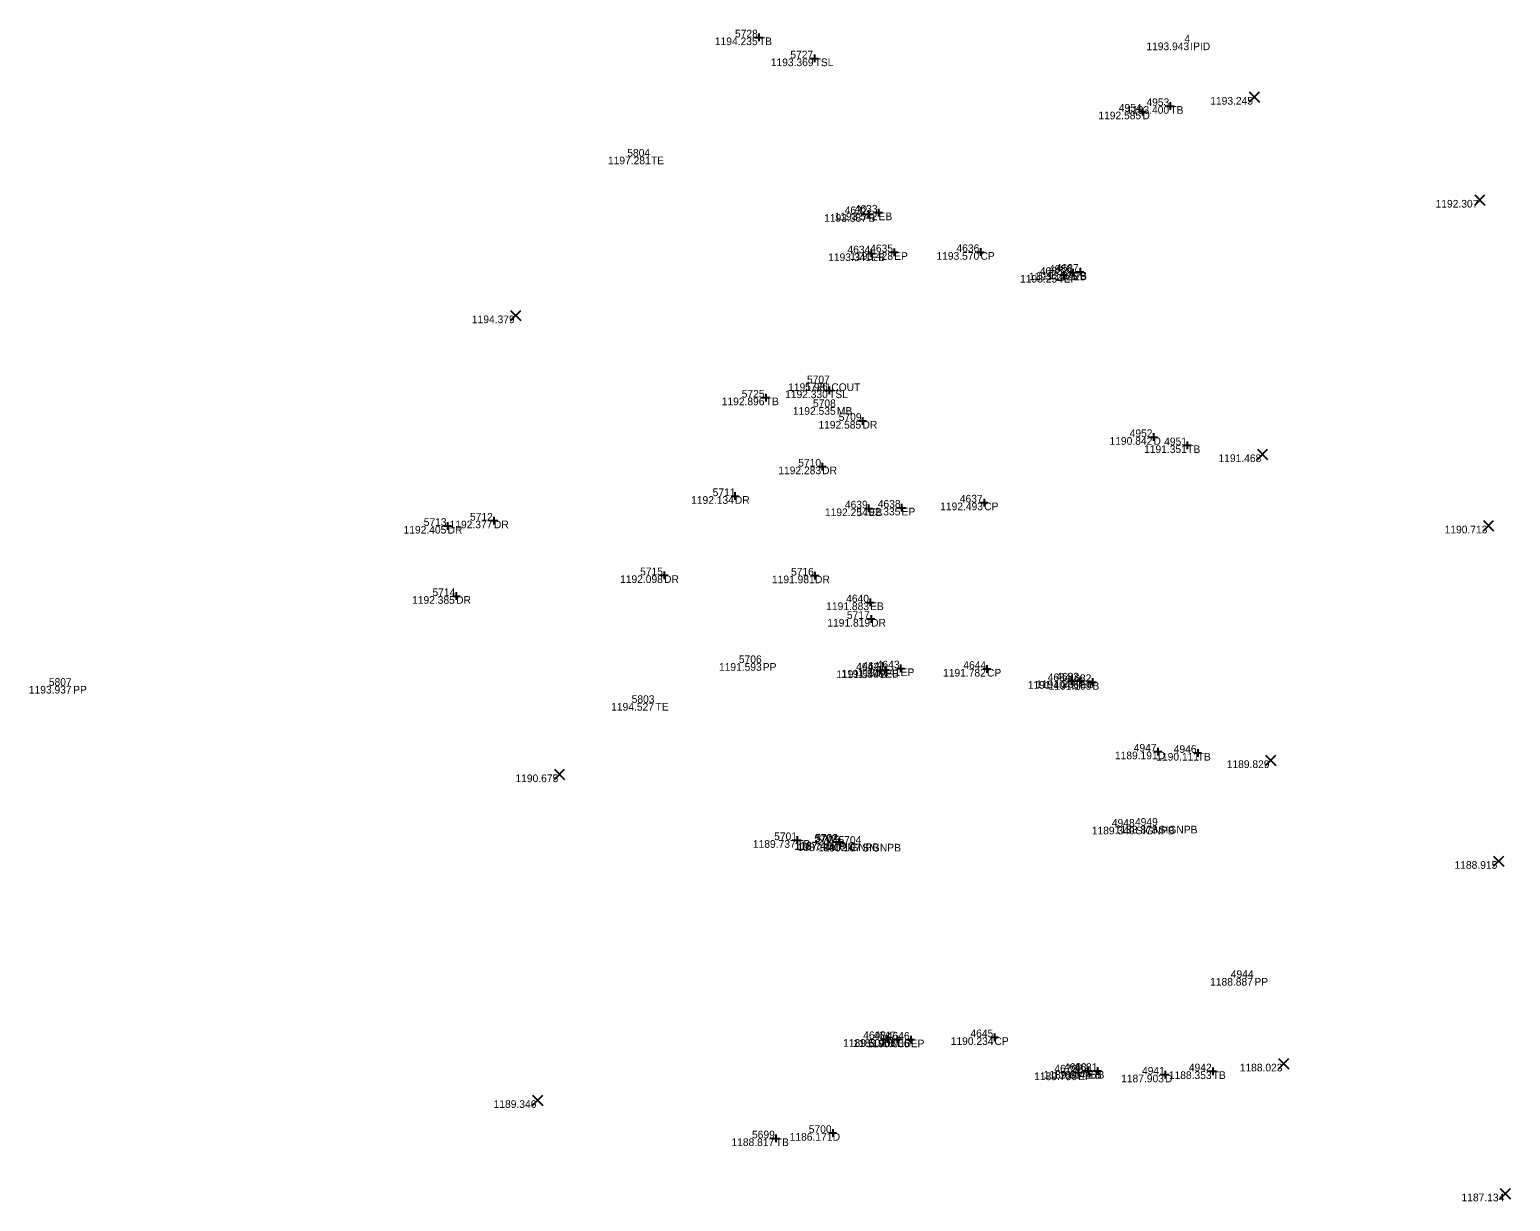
# Model space of a CAD drawing. Extents: x 2044997 to 2050342, y 455233 to 458054.
# Drawn here: x 2047524.4 to 2047717.5, y 456155.7 to 456308.4 of the extents above; entities that cross this region are included whole.
import ezdxf

# ---------------------------------------------------------------- set-up
doc = ezdxf.new("R2010")
doc.units = 0
for name, color, linetype in [('SV_X_Random_Point', 7, 'Continuous'), ('SV_X_Shot_Marker', 7, 'Continuous'), ('SV_X_Text_Comment', 7, 'Continuous'), ('SV_X_Text_Elevation', 7, 'Continuous'), ('SV_X_Text_Name', 7, 'Continuous')]:
    doc.layers.add(name, color=color, linetype=linetype)

msp = doc.modelspace()

# ---------------------------------------------------------------- linework, layer by layer
at = {"layer": 'SV_X_Random_Point'}
for p, q in [((2047683.45, 456298.97), (2047684.78, 456300.31)), ((2047683.45, 456300.31), (2047684.78, 456298.97)), ((2047712.86, 456285.55), (2047714.19, 456286.89)), ((2047712.86, 456286.89), (2047714.19, 456285.55)), ((2047587.15, 456270.48), (2047588.49, 456271.81)), ((2047587.15, 456271.81), (2047588.49, 456270.48)), ((2047684.52, 456252.38), (2047685.85, 456253.72)), ((2047684.52, 456253.72), (2047685.85, 456252.38)), ((2047713.99, 456243.08), (2047715.32, 456244.41)), ((2047713.99, 456244.41), (2047715.32, 456243.08)), ((2047685.57, 456212.49), (2047686.91, 456213.82)), ((2047685.57, 456213.82), (2047686.91, 456212.49)), ((2047592.86, 456210.65), (2047594.19, 456211.99)), ((2047592.86, 456211.99), (2047594.19, 456210.65)), ((2047715.3, 456199.35), (2047716.63, 456200.69)), ((2047715.3, 456200.69), (2047716.63, 456199.35)), ((2047687.26, 456172.94), (2047688.6, 456174.28)), ((2047687.26, 456174.28), (2047688.6, 456172.94)), ((2047590.01, 456168.18), (2047591.34, 456169.52)), ((2047590.01, 456169.52), (2047591.34, 456168.18)), ((2047716.17, 456156.01), (2047717.5, 456157.35)), ((2047716.17, 456157.35), (2047717.5, 456156.01))]:
    msp.add_line(p, q, dxfattribs=at)
at = {"layer": 'SV_X_Shot_Marker'}
for p, q in [((2047619.02, 456307.4), (2047620.02, 456307.4)), ((2047619.52, 456307.9), (2047619.52, 456306.9)), ((2047619.52, 456307.4), (2047619.52, 456307.4)), ((2047626.28, 456304.66), (2047627.28, 456304.66)), ((2047626.78, 456305.16), (2047626.78, 456304.16)), ((2047626.78, 456304.66), (2047626.78, 456304.66)), ((2047672.66, 456298.45), (2047673.66, 456298.45)), ((2047673.16, 456298.95), (2047673.16, 456297.95)), ((2047673.16, 456298.45), (2047673.16, 456298.45)), ((2047669.03, 456297.73), (2047670.03, 456297.73)), ((2047669.53, 456298.23), (2047669.53, 456297.23)), ((2047669.53, 456297.73), (2047669.53, 456297.73)), ((2047633.81, 456284.87), (2047633.81, 456283.87)), ((2047635.12, 456285.07), (2047635.12, 456284.07)), ((2047633.31, 456284.37), (2047634.31, 456284.37)), ((2047633.81, 456284.37), (2047633.81, 456284.37)), ((2047634.62, 456284.57), (2047635.62, 456284.57)), ((2047635.12, 456284.57), (2047635.12, 456284.57)), ((2047633.66, 456279.25), (2047634.66, 456279.25)), ((2047634.16, 456279.75), (2047634.16, 456278.75)), ((2047634.16, 456279.25), (2047634.16, 456279.25)), ((2047636.66, 456279.4), (2047637.66, 456279.4)), ((2047637.16, 456279.9), (2047637.16, 456278.9)), ((2047637.16, 456279.4), (2047637.16, 456279.4)), ((2047647.91, 456279.42), (2047648.91, 456279.42)), ((2047648.41, 456279.92), (2047648.41, 456278.92)), ((2047648.41, 456279.42), (2047648.41, 456279.42)), ((2047660.46, 456277.24), (2047660.46, 456276.24)), ((2047661.4, 456277.35), (2047661.4, 456276.35)), ((2047658.77, 456276.44), (2047659.77, 456276.44)), ((2047659.27, 456276.94), (2047659.27, 456275.94)), ((2047659.27, 456276.44), (2047659.27, 456276.44)), ((2047659.96, 456276.74), (2047660.96, 456276.74)), ((2047660.46, 456276.74), (2047660.46, 456276.74)), ((2047660.9, 456276.85), (2047661.9, 456276.85)), ((2047661.4, 456276.85), (2047661.4, 456276.85)), ((2047628.67, 456261.88), (2047628.67, 456260.88)), ((2047619.91, 456260.45), (2047620.91, 456260.45)), ((2047620.41, 456260.95), (2047620.41, 456259.95)), ((2047620.41, 456260.45), (2047620.41, 456260.45)), ((2047628.17, 456261.38), (2047629.17, 456261.38)), ((2047628.67, 456261.38), (2047628.67, 456261.38)), ((2047633.03, 456257.91), (2047633.03, 456256.91)), ((2047632.53, 456257.41), (2047633.53, 456257.41)), ((2047633.03, 456257.41), (2047633.03, 456257.41)), ((2047670.47, 456255.3), (2047671.47, 456255.3)), ((2047670.97, 456255.8), (2047670.97, 456254.8)), ((2047670.97, 456255.3), (2047670.97, 456255.3)), ((2047674.86, 456254.23), (2047675.86, 456254.23)), ((2047675.36, 456254.73), (2047675.36, 456253.73)), ((2047675.36, 456254.23), (2047675.36, 456254.23)), ((2047627.27, 456251.46), (2047628.27, 456251.46)), ((2047627.77, 456251.96), (2047627.77, 456250.96)), ((2047627.77, 456251.46), (2047627.77, 456251.46)), ((2047615.89, 456247.6), (2047616.89, 456247.6)), ((2047616.39, 456248.1), (2047616.39, 456247.1)), ((2047616.39, 456247.6), (2047616.39, 456247.6)), ((2047633.83, 456246.5), (2047633.83, 456245.5)), ((2047638.13, 456246.59), (2047638.13, 456245.59)), ((2047648.39, 456246.77), (2047649.39, 456246.77)), ((2047648.89, 456247.27), (2047648.89, 456246.27)), ((2047648.89, 456246.77), (2047648.89, 456246.77)), ((2047584.47, 456244.41), (2047585.47, 456244.41)), ((2047584.97, 456244.91), (2047584.97, 456243.91)), ((2047584.97, 456244.41), (2047584.97, 456244.41)), ((2047633.33, 456246), (2047634.33, 456246)), ((2047633.83, 456246), (2047633.83, 456246)), ((2047637.63, 456246.09), (2047638.63, 456246.09)), ((2047638.13, 456246.09), (2047638.13, 456246.09)), ((2047578.43, 456243.72), (2047579.43, 456243.72)), ((2047578.93, 456244.22), (2047578.93, 456243.22)), ((2047578.93, 456243.72), (2047578.93, 456243.72)), ((2047606.66, 456237.28), (2047607.66, 456237.28)), ((2047607.16, 456237.78), (2047607.16, 456236.78)), ((2047607.16, 456237.28), (2047607.16, 456237.28)), ((2047626.33, 456237.25), (2047627.33, 456237.25)), ((2047626.83, 456237.75), (2047626.83, 456236.75)), ((2047626.83, 456237.25), (2047626.83, 456237.25)), ((2047580.05, 456235.07), (2047580.05, 456234.07)), ((2047579.55, 456234.57), (2047580.55, 456234.57)), ((2047580.05, 456234.57), (2047580.05, 456234.57)), ((2047633.52, 456233.75), (2047634.52, 456233.75)), ((2047634.02, 456234.25), (2047634.02, 456233.25)), ((2047634.02, 456233.75), (2047634.02, 456233.75)), ((2047633.65, 456231.6), (2047634.65, 456231.6)), ((2047634.15, 456232.1), (2047634.15, 456231.1)), ((2047634.15, 456231.6), (2047634.15, 456231.6)), ((2047635.31, 456225.38), (2047635.31, 456224.38)), ((2047636, 456225.46), (2047636, 456224.46)), ((2047637.5, 456225.15), (2047638.5, 456225.15)), ((2047638, 456225.65), (2047638, 456224.65)), ((2047638, 456225.15), (2047638, 456225.15)), ((2047648.76, 456225.08), (2047649.76, 456225.08)), ((2047649.26, 456225.58), (2047649.26, 456224.58)), ((2047649.26, 456225.08), (2047649.26, 456225.08)), ((2047634.81, 456224.88), (2047635.81, 456224.88)), ((2047635.31, 456224.88), (2047635.31, 456224.88)), ((2047635.5, 456224.96), (2047636.5, 456224.96)), ((2047636, 456224.96), (2047636, 456224.96)), ((2047659.77, 456223.49), (2047660.77, 456223.49)), ((2047660.27, 456223.99), (2047660.27, 456222.99)), ((2047660.27, 456223.49), (2047660.27, 456223.49)), ((2047660.9, 456223.57), (2047661.9, 456223.57)), ((2047661.4, 456224.07), (2047661.4, 456223.07)), ((2047661.4, 456223.57), (2047661.4, 456223.57)), ((2047662.51, 456223.37), (2047663.51, 456223.37)), ((2047663.01, 456223.87), (2047663.01, 456222.87)), ((2047663.01, 456223.37), (2047663.01, 456223.37)), ((2047671.05, 456214.3), (2047672.05, 456214.3)), ((2047671.55, 456214.8), (2047671.55, 456213.8)), ((2047671.55, 456214.3), (2047671.55, 456214.3)), ((2047676.23, 456214.13), (2047677.23, 456214.13)), ((2047676.73, 456214.63), (2047676.73, 456213.63)), ((2047676.73, 456214.13), (2047676.73, 456214.13)), ((2047624.01, 456202.76), (2047625.01, 456202.76)), ((2047624.51, 456203.26), (2047624.51, 456202.26)), ((2047624.51, 456202.76), (2047624.51, 456202.76)), ((2047629.47, 456202.55), (2047630.47, 456202.55)), ((2047629.97, 456203.05), (2047629.97, 456202.05)), ((2047629.97, 456202.55), (2047629.97, 456202.55)), ((2047635.73, 456176.82), (2047636.73, 456176.82)), ((2047636.23, 456177.32), (2047636.23, 456176.32)), ((2047636.23, 456176.82), (2047636.23, 456176.82)), ((2047637.06, 456176.8), (2047638.06, 456176.8)), ((2047637.56, 456177.3), (2047637.56, 456176.3)), ((2047637.56, 456176.8), (2047637.56, 456176.8)), ((2047638.82, 456176.75), (2047639.82, 456176.75)), ((2047639.32, 456177.25), (2047639.32, 456176.25)), ((2047639.32, 456176.75), (2047639.32, 456176.75)), ((2047649.73, 456177.06), (2047650.73, 456177.06)), ((2047650.23, 456177.56), (2047650.23, 456176.56)), ((2047650.23, 456177.06), (2047650.23, 456177.06)), ((2047661.14, 456172.97), (2047661.14, 456171.97)), ((2047662.43, 456173.18), (2047662.43, 456172.18)), ((2047663.68, 456173.17), (2047663.68, 456172.17)), ((2047678.69, 456173.12), (2047678.69, 456172.12)), ((2047660.64, 456172.47), (2047661.64, 456172.47)), ((2047661.14, 456172.47), (2047661.14, 456172.47)), ((2047661.93, 456172.68), (2047662.93, 456172.68)), ((2047662.43, 456172.68), (2047662.43, 456172.68)), ((2047663.18, 456172.67), (2047664.18, 456172.67)), ((2047663.68, 456172.67), (2047663.68, 456172.67)), ((2047671.97, 456172.19), (2047672.97, 456172.19)), ((2047672.47, 456172.69), (2047672.47, 456171.69)), ((2047672.47, 456172.19), (2047672.47, 456172.19)), ((2047678.19, 456172.62), (2047679.19, 456172.62)), ((2047678.69, 456172.62), (2047678.69, 456172.62)), ((2047621.22, 456163.88), (2047622.22, 456163.88)), ((2047621.72, 456164.38), (2047621.72, 456163.38)), ((2047621.72, 456163.88), (2047621.72, 456163.88)), ((2047628.64, 456164.58), (2047629.64, 456164.58)), ((2047629.14, 456165.08), (2047629.14, 456164.08)), ((2047629.14, 456164.58), (2047629.14, 456164.58))]:
    msp.add_line(p, q, dxfattribs=at)

# ---------------------------------------------------------------- texts
at = {"layer": 'SV_X_Text_Comment'}
for s, p in [('TB', (2047619.52, 456306.4)), ('IPID', (2047675.76, 456305.74)), ('TSL', (2047626.78, 456303.66)), ('TB', (2047673.16, 456297.45)), ('D', (2047669.53, 456296.73)), ('TE', (2047605.45, 456290.86)), ('B', (2047633.81, 456283.37)), ('EB', (2047635.12, 456283.57)), ('EB', (2047634.16, 456278.25)), ('EP', (2047637.16, 456278.4)), ('CP', (2047648.41, 456278.42)), ('EP', (2047659.27, 456275.44)), ('EB', (2047660.46, 456275.74)), ('B', (2047661.4, 456275.85)), ('COUT', (2047628.96, 456261.31)), ('TB', (2047620.41, 456259.45)), ('TSL', (2047628.67, 456260.38)), ('MB', (2047629.69, 456258.21)), ('DR', (2047633.03, 456256.41)), ('D', (2047670.97, 456254.3)), ('TB', (2047675.36, 456253.23)), ('DR', (2047627.77, 456250.46)), ('DR', (2047616.39, 456246.6)), ('CP', (2047648.89, 456245.77)), ('DR', (2047584.97, 456243.41)), ('EB', (2047633.83, 456245)), ('EP', (2047638.13, 456245.09)), ('DR', (2047578.93, 456242.72)), ('DR', (2047607.16, 456236.28)), ('DR', (2047626.83, 456236.25)), ('DR', (2047580.05, 456233.57)), ('EB', (2047634.02, 456232.75)), ('DR', (2047634.15, 456230.6)), ('PP', (2047620.03, 456224.84)), ('EP', (2047638, 456224.15)), ('CP', (2047649.26, 456224.08)), ('B', (2047635.31, 456223.88)), ('EB', (2047636, 456223.96)), ('EP', (2047660.27, 456222.49)), ('EB', (2047661.4, 456222.57)), ('B', (2047663.01, 456222.37)), ('PP', (2047530.11, 456221.87)), ('TE', (2047606.04, 456219.64)), ('D', (2047671.55, 456213.3)), ('TB', (2047676.73, 456213.13)), ('SIGNPB', (2047668.66, 456203.51)), ('SIGNPB', (2047671.65, 456203.63)), ('TB', (2047624.51, 456201.76)), ('PIO', (2047629.87, 456201.49)), ('D', (2047629.97, 456201.55)), ('SIGNPB', (2047630.17, 456201.33)), ('SIGNPB', (2047632.99, 456201.28)), ('PP', (2047684.13, 456183.79)), ('B', (2047636.23, 456175.82)), ('EB', (2047637.56, 456175.8)), ('EP', (2047639.32, 456175.75)), ('CP', (2047650.23, 456176.06)), ('EP', (2047661.14, 456171.47)), ('EB', (2047662.43, 456171.68)), ('B', (2047663.68, 456171.67)), ('D', (2047672.47, 456171.19)), ('TB', (2047678.69, 456171.62)), ('TB', (2047621.72, 456162.88)), ('D', (2047629.14, 456163.58))]:
    msp.add_text(s, height=1, dxfattribs=at).set_placement(p)
at = {"layer": 'SV_X_Text_Elevation'}
for s, p in [('1194.235', (2047613.78, 456306.4)), ('1193.943', (2047670.04, 456305.74)), ('1193.369', (2047621.07, 456303.66)), ('1193.400', (2047667.43, 456297.45)), ('1193.245', (2047678.37, 456298.64)), ('1192.585', (2047663.78, 456296.73)), ('1197.281', (2047599.84, 456290.86)), ('1192.307', (2047707.75, 456285.22)), ('1193.387', (2047628.03, 456283.37)), ('1193.542', (2047629.39, 456283.57)), ('1193.341', (2047628.55, 456278.25)), ('1193.428', (2047631.43, 456278.4)), ('1193.570', (2047642.67, 456278.42)), ('1193.254', (2047653.57, 456275.44)), ('1193.122', (2047654.73, 456275.74)), ('1192.849', (2047655.69, 456275.85)), ('1194.379', (2047582.1, 456270.15)), ('1191.981', (2047623.34, 456261.31)), ('1192.896', (2047614.67, 456259.45)), ('1192.330', (2047622.93, 456260.38)), ('1192.535', (2047623.95, 456258.21)), ('1192.585', (2047627.28, 456256.41)), ('1190.842', (2047665.24, 456254.3)), ('1191.351', (2047669.74, 456253.23)), ('1191.468', (2047679.45, 456252.05)), ('1192.283', (2047622.05, 456250.46)), ('1192.134', (2047610.68, 456246.6)), ('1192.493', (2047643.16, 456245.77)), ('1192.377', (2047579.19, 456243.41)), ('1192.254', (2047628.13, 456245)), ('1192.335', (2047632.39, 456245.09)), ('1192.405', (2047573.19, 456242.72)), ('1190.713', (2047708.93, 456242.75)), ('1192.098', (2047601.42, 456236.28)), ('1191.981', (2047621.22, 456236.25)), ('1192.385', (2047574.3, 456233.57)), ('1191.883', (2047628.3, 456232.75)), ('1191.819', (2047628.44, 456230.6)), ('1191.593', (2047614.31, 456224.84)), ('1191.641', (2047632.39, 456224.15)), ('1191.782', (2047643.53, 456224.08)), ('1191.544', (2047629.61, 456223.88)), ('1191.596', (2047630.26, 456223.96)), ('1191.404', (2047654.57, 456222.49)), ('1191.286', (2047655.66, 456222.57)), ('1191.109', (2047657.3, 456222.37)), ('1193.937', (2047524.33, 456221.87)), ('1194.527', (2047600.26, 456219.64)), ('1189.191', (2047665.94, 456213.3)), ('1190.111', (2047671.33, 456213.13)), ('1189.829', (2047680.52, 456212.16)), ('1190.675', (2047587.78, 456210.32)), ('1189.340', (2047662.92, 456203.51)), ('1188.878', (2047665.92, 456203.63)), ('1189.737', (2047618.74, 456201.76)), ('1187.410', (2047624.14, 456201.49)), ('1187.407', (2047624.2, 456201.55)), ('1187.241', (2047624.56, 456201.33)), ('1190.167', (2047627.22, 456201.28)), ('1188.915', (2047710.22, 456199.02)), ('1188.887', (2047678.35, 456183.79)), ('1189.502', (2047630.5, 456175.82)), ('1189.908', (2047631.83, 456175.8)), ('1190.006', (2047633.58, 456175.75)), ('1190.234', (2047644.53, 456176.06)), ('1188.023', (2047682.21, 456172.61)), ('1189.730', (2047655.41, 456171.47)), ('1189.617', (2047656.65, 456171.68)), ('1189.496', (2047657.95, 456171.67)), ('1187.903', (2047666.75, 456171.19)), ('1188.353', (2047672.97, 456171.62)), ('1189.346', (2047584.93, 456167.85)), ('1188.817', (2047615.94, 456162.88)), ('1186.171', (2047623.53, 456163.58)), ('1187.134', (2047711.13, 456155.68))]:
    msp.add_text(s, height=1, dxfattribs=at).set_placement(p)
at = {"layer": 'SV_X_Text_Name'}
for s, p in [('5728', (2047616.4, 456307.4)), ('4', (2047675, 456306.74)), ('5727', (2047623.62, 456304.66)), ('4954', (2047666.44, 456297.73)), ('4953', (2047670.05, 456298.45)), ('5804', (2047602.36, 456291.86)), ('4632', (2047630.7, 456284.37)), ('4633', (2047632.02, 456284.57)), ('4634', (2047631.07, 456279.25)), ('4635', (2047634.03, 456279.4)), ('4636', (2047645.28, 456279.42)), ('4685', (2047656.14, 456276.44)), ('4686', (2047657.34, 456276.74)), ('4687', (2047658.24, 456276.85)), ('5726', (2047625.54, 456261.38)), ('5707', (2047625.79, 456262.31)), ('5725', (2047617.28, 456260.45)), ('5708', (2047626.57, 456259.21)), ('5709', (2047629.93, 456257.41)), ('4952', (2047667.86, 456255.3)), ('4951', (2047672.36, 456254.23)), ('5710', (2047624.65, 456251.46)), ('5711', (2047613.49, 456247.6)), ('4639', (2047630.73, 456246)), ('4638', (2047635.02, 456246.09)), ('4637', (2047645.72, 456246.77)), ('5713', (2047575.82, 456243.72)), ('5712', (2047581.85, 456244.41)), ('5715', (2047604.03, 456237.28)), ('5716', (2047623.71, 456237.25)), ('5714', (2047576.96, 456234.57)), ('4640', (2047630.9, 456233.75)), ('5717', (2047630.99, 456231.6)), ('5706', (2047616.91, 456225.84)), ('4642', (2047632.2, 456224.88)), ('4641', (2047633, 456224.96)), ('4643', (2047634.89, 456225.15)), ('4644', (2047646.17, 456225.08)), ('5807', (2047526.94, 456222.87)), ('4684', (2047657.18, 456223.49)), ('4683', (2047658.29, 456223.57)), ('4682', (2047659.89, 456223.37)), ('5803', (2047602.93, 456220.64)), ('4947', (2047668.39, 456214.3)), ('4946', (2047673.61, 456214.13)), ('5701', (2047621.51, 456202.76)), ('4948', (2047665.54, 456204.51)), ('4949', (2047668.55, 456204.63)), ('5703', (2047626.76, 456202.49)), ('5702', (2047626.86, 456202.55)), ('5705', (2047627.04, 456202.33)), ('5704', (2047629.9, 456202.28)), ('4944', (2047681.04, 456184.79)), ('4648', (2047633.12, 456176.82)), ('4647', (2047634.4, 456176.8)), ('4646', (2047636.2, 456176.75)), ('4645', (2047647.1, 456177.06)), ('4679', (2047658.04, 456172.47)), ('4680', (2047659.31, 456172.68)), ('4681', (2047660.68, 456172.67)), ('4941', (2047669.47, 456172.19)), ('4942', (2047675.58, 456172.62)), ('5700', (2047626.02, 456164.58)), ('5699', (2047618.62, 456163.88))]:
    msp.add_text(s, height=1, dxfattribs=at).set_placement(p)

doc.saveas('drawing.dxf')
